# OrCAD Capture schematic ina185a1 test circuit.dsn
size A
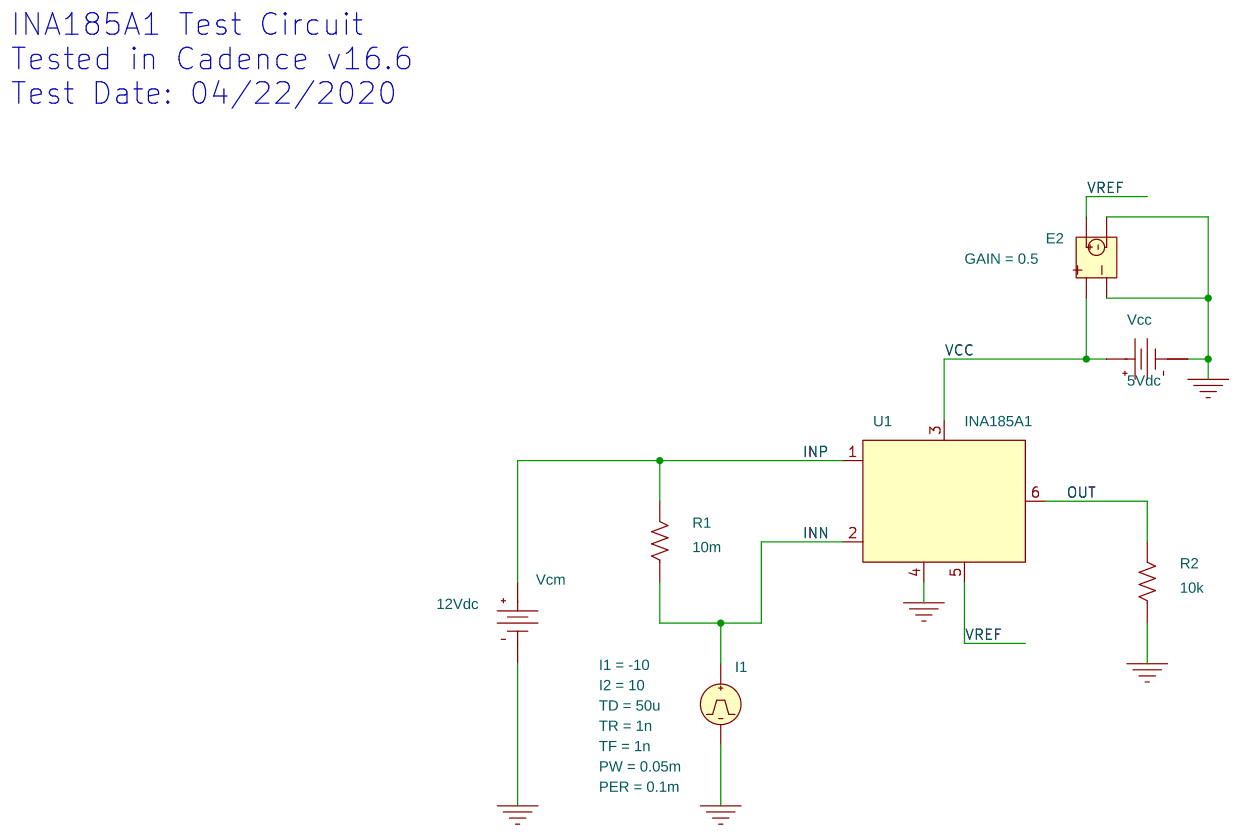
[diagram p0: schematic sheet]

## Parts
E2  E
I1  IPULSE
R1  10m  [AX/RC05]
R2  10k  [AX/RC05]
U1  INA185A1
Vcc  VDC
Vcm  VDC

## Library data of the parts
E2 = E: GAIN: 0.5
I1 = IPULSE: I1: -10; I2: 10; PER: 0.1m; PW: 0.05m; TD: 50u; TF: 1n; TR: 1n
R1 R2 = R
U1 = INA185A1
Vcc = VDC: DC: 5Vdc
Vcm = VDC: DC: 12Vdc

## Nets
VCC: E2.1 U1.3(VCC) Vcc.0(+)
0: E2.2 E2.4 I1.2(-) R2.1 U1.4(GND) Vcc.1(-) Vcm.1(-)
INN: I1.1(+) R1.1 U1.2(INN)
INP: R1.2 U1.1(INP) Vcm.0(+)
OUT: R2.2 U1.6(OUT)
VREF: E2.3 U1.5(REF)

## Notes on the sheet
- INA185A1 Test Circuit
  Tested in Cadence v16.6
  Test Date: 04/22/2020
